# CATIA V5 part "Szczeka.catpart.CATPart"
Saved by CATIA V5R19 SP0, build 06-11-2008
Part number: Szczeka
Revision: ANY
Definition: Jaw
Source: Unknown
Bounding box of the stored display mesh (mm): x 0 to 125, y 0 to 109, z -18 to 124
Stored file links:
  G:\Catia\CD\Ustawienia\Imadlo\Szczeka.catpart.CATPart
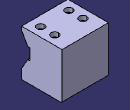
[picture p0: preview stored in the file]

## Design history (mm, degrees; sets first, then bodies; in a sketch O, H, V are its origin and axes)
Body1 "Imported1" (main body)
  Solid1 "Manifold Solid #2513": solid without history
